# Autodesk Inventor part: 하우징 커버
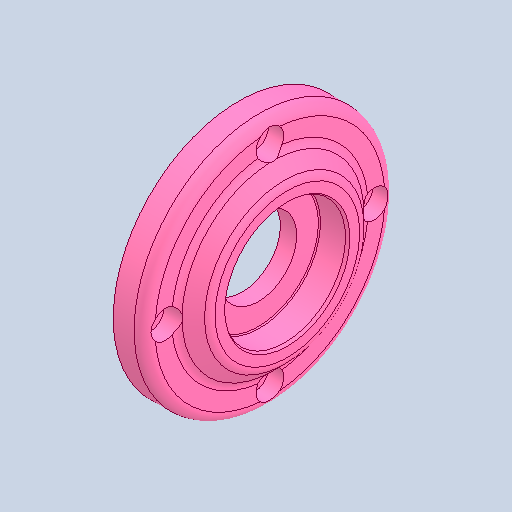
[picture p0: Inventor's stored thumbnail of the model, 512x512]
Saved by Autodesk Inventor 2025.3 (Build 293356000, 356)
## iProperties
Created: 2026-01
Part Number: 하우징 커버
Material: 알루미늄 6061
Document SubType Name: Modeling
Designer: PC-13
Density: 2.7 g/cm^3
Appearance: 기본값
Author: jhkim
Sending System: Autodesk Inventor 2026
Preprocessor: ST-DEVELOPER v20.1
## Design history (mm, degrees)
feature "솔리드1"
node "솔리드2"
